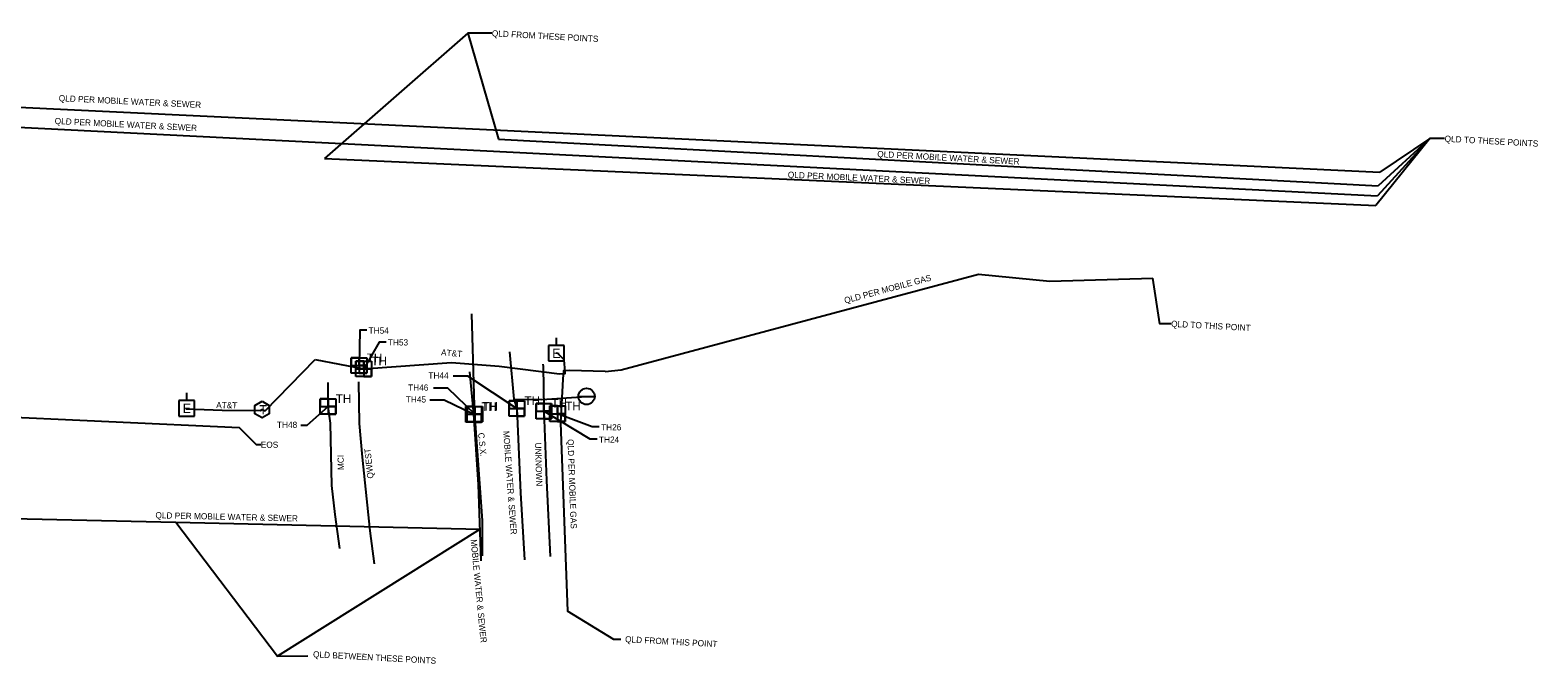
# Model space of a CAD drawing. Extents: x 1797765 to 1816938, y 246120 to 250965.
# Drawn here: x 1799084.8 to 1799572.2, y 248802.7 to 249007.4 of the extents above; entities that cross this region are included whole.
import ezdxf

# ---------------------------------------------------------------- set-up
doc = ezdxf.new("R2010")
doc.units = 0
for name, color, linetype in [('EX-OHUT-ELEC', 7, 'Continuous'), ('EX-UGUT-ELEC-X-CARDNO-X', 7, 'Continuous'), ('EX-UGUT-FOC-X-CARDNO-X', 7, 'Continuous'), ('EX-UGUT-GAS_MAIN-X-CARDNO-X', 7, 'Continuous'), ('EX-UGUT-PHONE', 7, 'Continuous'), ('EX-UGUT-TELE-X-CARDNO-X', 7, 'Continuous'), ('EX-UGUT-TXT', 7, 'Continuous'), ('EX-UGUT-WATER', 7, 'Continuous'), ('EX-UGUT-WATER-X-CARDNO-X', 7, 'Continuous'), ('EX-UGUT-X-CARDNO-X', 7, 'Continuous'), ('SU_QLATestHole_ep', 7, 'Continuous'), ('UG-BURIED SANITARY SEWER', 7, 'Continuous')]:
    doc.layers.add(name, color=color, linetype=linetype)

msp = doc.modelspace()

# ---------------------------------------------------------------- linework, layer by layer
at = {"layer": 'EX-OHUT-ELEC'}
for p, q in [((1799254.87, 248908.01), (1799254.87, 248905.51)), ((1799252.37, 248905.51), (1799252.37, 248900.51)), ((1799257.37, 248900.51), (1799257.37, 248905.51)), ((1799252.37, 248900.51), (1799257.37, 248900.51)), ((1799132.89, 248887.72), (1799132.89, 248882.72)), ((1799135.39, 248890.22), (1799135.39, 248887.72)), ((1799137.89, 248882.72), (1799137.89, 248887.72)), ((1799132.89, 248882.72), (1799137.89, 248882.72))]:
    msp.add_line(p, q, dxfattribs=at)
for points in [[(1799257.37, 248905.51), (1799254.87, 248905.51), (1799252.37, 248905.51)], [(1799137.89, 248887.72), (1799135.39, 248887.72), (1799132.89, 248887.72)]]:
    msp.add_lwpolyline(points, dxfattribs=at)
at = {"layer": 'EX-UGUT-ELEC-X-CARDNO-X'}
msp.add_lwpolyline([(1799231.06, 248837.53), (1799230.97, 248849), (1799228.53, 248883.32), (1799228.45, 248886.03), (1799227.57, 248915.76)], dxfattribs=at)
at = {"layer": 'EX-UGUT-FOC-X-CARDNO-X'}
for points in [[(1799184.86, 248839.88), (1799183.39, 248850.93), (1799182.34, 248860.25), (1799181.88, 248880.47), (1799181.09, 248885.81), (1799181.18, 248893.61)], [(1799196.09, 248835.01), (1799194.71, 248845.68), (1799192.26, 248869.48), (1799191.25, 248880.31), (1799191.03, 248893.78)]]:
    msp.add_lwpolyline(points, dxfattribs=at)
at = {"layer": 'EX-UGUT-GAS_MAIN-X-CARDNO-X'}
for points in [[(1799270.66, 248897.07), (1799275.9, 248897.67), (1799391.36, 248928.61), (1799414.38, 248926.3), (1799447.7, 248927.31)], [(1799270.66, 248897.07), (1799259.1, 248897.47), (1799257.25, 248897.36), (1799256.98, 248894.64), (1799256.25, 248880.5), (1799258.45, 248819.65)]]:
    msp.add_lwpolyline(points, dxfattribs=at)
at = {"layer": 'EX-UGUT-PHONE'}
msp.add_lwpolyline([(1799159.79, 248887.49), (1799162.11, 248886.15), (1799162.11, 248883.48), (1799159.79, 248882.14), (1799157.47, 248883.48), (1799157.47, 248886.15)], close=True, dxfattribs=at)
at = {"layer": 'EX-UGUT-TELE-X-CARDNO-X'}
for points in [[(1799135.39, 248885.22), (1799135.21, 248885.01), (1799146.91, 248884.67), (1799159.23, 248884.54), (1799159.79, 248884.82), (1799160.79, 248884.44), (1799176.93, 248900.98)], [(1799176.93, 248900.98), (1799192.63, 248897.99), (1799221.03, 248900.06), (1799236.45, 248898.82), (1799255.96, 248896.32), (1799257.79, 248896.52), (1799257.68, 248898.29), (1799257.43, 248900.86), (1799255.38, 248902.93), (1799254.87, 248903.01)]]:
    msp.add_lwpolyline(points, dxfattribs=at)
at = {"layer": 'EX-UGUT-TXT'}
for p, q in [((1799226.31, 249006.42), (1799179.98, 248965.93)), ((1799537.24, 248972.36), (1799519.84, 248950.76)), ((1799537.24, 248972.36), (1799520.3, 248953.93)), ((1799537.24, 248972.36), (1799520.55, 248957.09)), ((1799230.25, 248846.17), (1799164.71, 248805.15))]:
    msp.add_line(p, q, dxfattribs=at)
for points in [[(1799234.05, 249006.42), (1799226.31, 249006.42), (1799236.21, 248972.23)], [(1799542.04, 248972.36), (1799537.24, 248972.36), (1799521.08, 248961.5)], [(1799453.65, 248912.56), (1799449.98, 248912.56), (1799447.7, 248927.31)], [(1799193.61, 248910.47), (1799191.35, 248910.47), (1799191.11, 248899.03)], [(1799199.84, 248906.64), (1799197.58, 248906.64), (1799192.63, 248897.99)], [(1799215.15, 248891.8), (1799219.74, 248891.8), (1799228.53, 248883.32)], [(1799221.54, 248895.71), (1799226.13, 248895.71), (1799242.1, 248885.16)], [(1799213.99, 248887.98), (1799218.58, 248887.98), (1799228.17, 248883.28)], [(1799172.33, 248879.78), (1799174.37, 248879.78), (1799181.09, 248885.81)], [(1799268.07, 248875.22), (1799265.81, 248875.22), (1799250.82, 248884.31)], [(1799268.76, 248879.21), (1799266.5, 248879.21), (1799255.25, 248883.48)], [(1799159.35, 248873.45), (1799157.93, 248873.45), (1799152.4, 248879.01)], [(1799131.89, 248848.4), (1799164.71, 248805.15), (1799174.54, 248805.22)], [(1799275.71, 248810.56), (1799273.45, 248810.56), (1799258.45, 248819.65)]]:
    msp.add_lwpolyline(points, dxfattribs=at)
at = {"layer": 'EX-UGUT-WATER'}
msp.add_line((1799262.04, 248889.07), (1799267.29, 248889.07), dxfattribs=at)
msp.add_circle((1799264.67, 248889.07), 2.62, dxfattribs=at)
at = {"layer": 'EX-UGUT-WATER-X-CARDNO-X'}
for p, q in [((1799236.21, 248972.23), (1799520.55, 248957.09)), ((1799131.89, 248848.4), (1799230.25, 248846.17))]:
    msp.add_line(p, q, dxfattribs=at)
for points in [[(1798988.9, 248899.32), (1798995.21, 248986.66), (1799521.08, 248961.5)], [(1799239.78, 248903.5), (1799241.11, 248888.14), (1799242.1, 248885.16), (1799243.32, 248857.95), (1799244.63, 248836.23)], [(1799230.64, 248835.92), (1799229.71, 248860.59), (1799228.17, 248883.28), (1799226.96, 248896.96)], [(1799241.13, 248888.21), (1799250.2, 248888.04), (1799264.67, 248889.07)], [(1798685.79, 248870.12), (1798781.34, 248863.77), (1798796.52, 248862.81), (1798808.44, 248862.33), (1798851.84, 248859.62), (1798881.05, 248857.49), (1798930.39, 248854.37), (1798981.68, 248853.31), (1798986.59, 248853.5), (1798988.34, 248853.31), (1798989.48, 248853.2), (1798991.29, 248853.29), (1798992.11, 248853.31), (1798993.09, 248853.22), (1799030.93, 248850.68), (1799131.89, 248848.4)]]:
    msp.add_lwpolyline(points, dxfattribs=at)
at = {"layer": 'EX-UGUT-X-CARDNO-X'}
for points in [[(1799250.56, 248899.46), (1799250.63, 248898.74), (1799250.85, 248885.16), (1799250.82, 248884.31), (1799251.74, 248861.9), (1799252.88, 248837.31)], [(1798805.02, 248892.23), (1798821.39, 248891.83), (1798839.2, 248890.25), (1798840.43, 248890.19), (1798849.89, 248889.84), (1798862.58, 248889.1), (1798901.44, 248887.68), (1798938.68, 248886.37), (1799031.01, 248883.21), (1799067.99, 248882.95), (1799152.4, 248879.01)]]:
    msp.add_lwpolyline(points, dxfattribs=at)
at = {"layer": 'SU_QLATestHole_ep'}
for p, q in [((1799188.61, 248901.53), (1799193.61, 248901.53)), ((1799188.61, 248896.53), (1799188.61, 248901.53)), ((1799188.61, 248901.53), (1799188.61, 248899.03)), ((1799191.11, 248901.53), (1799188.61, 248901.53)), ((1799191.11, 248901.53), (1799191.11, 248896.53)), ((1799191.11, 248899.03), (1799191.11, 248901.53)), ((1799193.61, 248901.53), (1799193.61, 248896.53)), ((1799188.61, 248899.03), (1799193.61, 248899.03)), ((1799188.61, 248899.03), (1799191.11, 248899.03)), ((1799193.61, 248896.53), (1799188.61, 248896.53)), ((1799190.13, 248900.49), (1799195.13, 248900.49)), ((1799190.13, 248895.49), (1799190.13, 248900.49)), ((1799190.13, 248900.49), (1799190.13, 248897.99)), ((1799192.63, 248900.49), (1799190.13, 248900.49)), ((1799190.13, 248897.99), (1799195.13, 248897.99)), ((1799190.13, 248897.99), (1799192.63, 248897.99)), ((1799193.61, 248899.03), (1799191.11, 248899.03)), ((1799191.11, 248899.03), (1799191.11, 248896.53)), ((1799191.11, 248896.53), (1799193.61, 248896.53)), ((1799192.63, 248900.49), (1799192.63, 248895.49)), ((1799192.63, 248897.99), (1799192.63, 248900.49)), ((1799195.13, 248897.99), (1799192.63, 248897.99)), ((1799192.63, 248897.99), (1799192.63, 248895.49)), ((1799193.61, 248896.53), (1799193.61, 248899.03)), ((1799195.13, 248900.49), (1799195.13, 248895.49)), ((1799195.13, 248895.49), (1799195.13, 248897.99)), ((1799195.13, 248895.49), (1799190.13, 248895.49)), ((1799192.63, 248895.49), (1799195.13, 248895.49)), ((1799178.59, 248888.31), (1799183.59, 248888.31)), ((1799178.59, 248883.31), (1799178.59, 248888.31)), ((1799178.59, 248888.31), (1799178.59, 248885.81)), ((1799181.09, 248888.31), (1799178.59, 248888.31)), ((1799181.09, 248888.31), (1799181.09, 248883.31)), ((1799181.09, 248885.81), (1799181.09, 248888.31)), ((1799183.59, 248888.31), (1799183.59, 248883.31)), ((1799239.6, 248887.66), (1799244.6, 248887.66)), ((1799239.6, 248882.66), (1799239.6, 248887.66)), ((1799239.6, 248887.66), (1799239.6, 248885.16)), ((1799242.1, 248887.66), (1799239.6, 248887.66)), ((1799242.1, 248887.66), (1799242.1, 248882.66)), ((1799242.1, 248885.16), (1799242.1, 248887.66)), ((1799244.6, 248887.66), (1799244.6, 248882.66)), ((1799248.32, 248886.81), (1799253.32, 248886.81)), ((1799248.32, 248881.81), (1799248.32, 248886.81)), ((1799248.32, 248886.81), (1799248.32, 248884.31)), ((1799250.82, 248886.81), (1799248.32, 248886.81)), ((1799250.82, 248886.81), (1799250.82, 248881.81)), ((1799250.82, 248884.31), (1799250.82, 248886.81)), ((1799253.32, 248886.81), (1799253.32, 248881.81)), ((1799178.59, 248885.81), (1799183.59, 248885.81)), ((1799178.59, 248885.81), (1799181.09, 248885.81)), ((1799183.59, 248883.31), (1799178.59, 248883.31)), ((1799183.59, 248885.81), (1799181.09, 248885.81)), ((1799181.09, 248885.81), (1799181.09, 248883.31)), ((1799181.09, 248883.31), (1799183.59, 248883.31)), ((1799183.59, 248883.31), (1799183.59, 248885.81)), ((1799225.67, 248885.78), (1799230.67, 248885.78)), ((1799225.67, 248880.78), (1799225.67, 248885.78)), ((1799225.67, 248885.78), (1799225.67, 248883.28)), ((1799228.17, 248885.78), (1799225.67, 248885.78)), ((1799225.67, 248883.28), (1799230.67, 248883.28)), ((1799225.67, 248883.28), (1799228.17, 248883.28)), ((1799226.03, 248885.82), (1799231.03, 248885.82)), ((1799226.03, 248880.82), (1799226.03, 248885.82)), ((1799226.03, 248885.82), (1799226.03, 248883.32)), ((1799228.53, 248885.82), (1799226.03, 248885.82)), ((1799226.03, 248883.32), (1799231.03, 248883.32)), ((1799226.03, 248883.32), (1799228.53, 248883.32)), ((1799228.17, 248885.78), (1799228.17, 248880.78)), ((1799228.17, 248883.28), (1799228.17, 248885.78)), ((1799230.67, 248883.28), (1799228.17, 248883.28)), ((1799228.17, 248883.28), (1799228.17, 248880.78)), ((1799228.53, 248885.82), (1799228.53, 248880.82)), ((1799228.53, 248883.32), (1799228.53, 248885.82)), ((1799231.03, 248883.32), (1799228.53, 248883.32)), ((1799228.53, 248883.32), (1799228.53, 248880.82)), ((1799230.67, 248885.78), (1799230.67, 248880.78)), ((1799230.67, 248880.78), (1799230.67, 248883.28)), ((1799231.03, 248885.82), (1799231.03, 248880.82)), ((1799231.03, 248880.82), (1799231.03, 248883.32)), ((1799239.6, 248885.16), (1799244.6, 248885.16)), ((1799239.6, 248885.16), (1799242.1, 248885.16)), ((1799244.6, 248882.66), (1799239.6, 248882.66)), ((1799244.6, 248885.16), (1799242.1, 248885.16)), ((1799242.1, 248885.16), (1799242.1, 248882.66)), ((1799242.1, 248882.66), (1799244.6, 248882.66)), ((1799244.6, 248882.66), (1799244.6, 248885.16)), ((1799248.32, 248884.31), (1799253.32, 248884.31)), ((1799248.32, 248884.31), (1799250.82, 248884.31)), ((1799253.32, 248881.81), (1799248.32, 248881.81)), ((1799253.32, 248884.31), (1799250.82, 248884.31)), ((1799250.82, 248884.31), (1799250.82, 248881.81)), ((1799250.82, 248881.81), (1799253.32, 248881.81)), ((1799252.75, 248885.98), (1799257.75, 248885.98)), ((1799252.75, 248880.98), (1799252.75, 248885.98)), ((1799252.75, 248885.98), (1799252.75, 248883.48)), ((1799255.25, 248885.98), (1799252.75, 248885.98)), ((1799252.75, 248883.48), (1799257.75, 248883.48)), ((1799252.75, 248883.48), (1799255.25, 248883.48)), ((1799253.32, 248881.81), (1799253.32, 248884.31)), ((1799255.25, 248885.98), (1799255.25, 248880.98)), ((1799255.25, 248883.48), (1799255.25, 248885.98)), ((1799257.75, 248883.48), (1799255.25, 248883.48)), ((1799255.25, 248883.48), (1799255.25, 248880.98)), ((1799257.75, 248885.98), (1799257.75, 248880.98)), ((1799257.75, 248880.98), (1799257.75, 248883.48)), ((1799230.67, 248880.78), (1799225.67, 248880.78)), ((1799231.03, 248880.82), (1799226.03, 248880.82)), ((1799228.17, 248880.78), (1799230.67, 248880.78)), ((1799228.53, 248880.82), (1799231.03, 248880.82)), ((1799257.75, 248880.98), (1799252.75, 248880.98)), ((1799255.25, 248880.98), (1799257.75, 248880.98))]:
    msp.add_line(p, q, dxfattribs=at)
at = {"layer": 'UG-BURIED SANITARY SEWER'}
msp.add_line((1799179.98, 248965.93), (1799519.84, 248950.76), dxfattribs=at)
msp.add_lwpolyline([(1798863.32, 248905.48), (1798869.73, 248986.74), (1799520.3, 248953.93)], dxfattribs=at)

# ---------------------------------------------------------------- texts
at = {"layer": 'EX-OHUT-ELEC'}
for p in [(1799253.58, 248901.51), (1799134.1, 248883.72)]:
    msp.add_text('E', height=3, dxfattribs=at).set_placement(p)
at = {"layer": 'EX-UGUT-PHONE'}
msp.add_text('T', height=3, dxfattribs=at).set_placement((1799158.92, 248883.24))
at = {"layer": 'EX-UGUT-TXT'}
for s, rotation, p in [('QLD FROM THESE POINTS', 356.9533, (1799234, 249005.42)), ('QLD PER MOBILE WATER & SEWER', 357.2603, (1799094, 248984.48)), ('QLD PER MOBILE WATER & SEWER', 357.1131, (1799092.69, 248977.11)), ('QLD TO THESE POINTS', 356.9533, (1799541.99, 248971.37)), ('QLD PER MOBILE WATER & SEWER', 356.9533, (1799358.59, 248966.42)), ('QLD PER MOBILE WATER & SEWER', 357.4454, (1799329.69, 248959.73)), ('QLD PER MOBILE GAS', 14.9992, (1799348.26, 248919.04)), ('QLD TO THIS POINT', 356.9533, (1799453.59, 248911.56)), ('AT&T', 355.3849, (1799217.56, 248902.32)), ('AT&T', 359.2726, (1799144.92, 248885.28)), ('C.S.X.', 275.5817, (1799229.58, 248877.24)), ('MOBILE WATER & SEWER', 274.2009, (1799237.7, 248877.84)), ('QWEST', 95.875, (1799195.81, 248862.62)), ('UNKNOWN', 271.7143, (1799247.98, 248874.11)), ('QLD PER MOBILE GAS', 272.0746, (1799258.5, 248875.23)), ('MCI', 91.3034, (1799186.24, 248865.29)), ('QLD PER MOBILE WATER & SEWER', 358.7034, (1799125.27, 248849.69)), ('MOBILE WATER & SEWER', 275.5817, (1799227.17, 248842.76)), ('QLD FROM THIS POINT', 356.9533, (1799277.08, 248809.63)), ('QLD BETWEEN THESE POINTS', 356.9533, (1799176.2, 248804.77))]:
    msp.add_text(s, height=2, rotation=rotation, dxfattribs=at).set_placement(p)
for s, p in [('TH54', (1799194.21, 248909.35)), ('TH53', (1799200.44, 248905.52)), ('TH44', (1799213.52, 248894.83)), ('TH46', (1799206.98, 248890.92)), ('TH45', (1799206.23, 248887.1)), ('TH48', (1799164.58, 248878.9)), ('TH26', (1799269.36, 248878.09)), ('EOS', (1799159.35, 248872.45)), ('TH24', (1799268.67, 248874.1))]:
    msp.add_text(s, height=2, dxfattribs=at).set_placement(p)
at = {"layer": 'SU_QLATestHole_ep'}
for p in [(1799193.61, 248900.13), (1799195.13, 248899.09), (1799183.59, 248886.91), (1799230.67, 248884.38), (1799231.03, 248884.42), (1799244.6, 248886.26), (1799253.32, 248885.41), (1799257.75, 248884.58)]:
    msp.add_text('TH', height=2.8, dxfattribs=at).set_placement(p)

doc.saveas('drawing.dxf')
